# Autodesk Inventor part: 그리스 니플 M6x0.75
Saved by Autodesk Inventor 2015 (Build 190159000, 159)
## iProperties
Created: 2024-12
Part Number: 그리스 니플 M6x0.75
Material: 일반
Document SubType Name: Modeling
Designer: 102-5
Density: 1 g/cm^3
Appearance: 기본값
Author: 102-5
Author: jhkim
Description: 윤활 니플, 원추 유형 A
Creation Date: 2024-11-28
Sending System: Autodesk Inventor 2025
Preprocessor: ST-DEVELOPER v20
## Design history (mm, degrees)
node "그리스 니플 M6x0.751"
body "Solid1"
node "기준1"
